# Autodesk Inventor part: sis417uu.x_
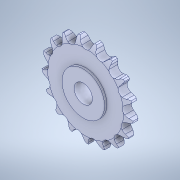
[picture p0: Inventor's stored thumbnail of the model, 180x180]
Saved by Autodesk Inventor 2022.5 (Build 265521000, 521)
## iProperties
Created: 2022-04
Part Number: sis417uu.x_
Material: 一般
Document SubType Name: Modeling
Designer: ImaoCorp
Density: 1 g/cm^3
Appearance: 既定
Sending System: SOLIDWORKS 2020-2020296
MC: AMD64
MC_MODEL: Intel64 Family 6 Model 60 Stepping 3, GenuineIntel
OS: Windows_NT
FRU: Parasolid Version 31.1, build 290,  3- 9-2020
FORMAT: text
GUISE: transmit
KEY: sis417uu
FILE: sis417uu.x_t
DATE: Thu Apr 21 11:15:17 2022
Author: ImaoCorp
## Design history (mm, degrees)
feature "Base1"
node "ソリッド1"
